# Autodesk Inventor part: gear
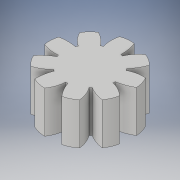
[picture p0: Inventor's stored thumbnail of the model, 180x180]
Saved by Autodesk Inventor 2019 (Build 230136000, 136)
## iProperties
Created: 2019-11
Part Number: gear
Material: Generic
Document SubType Name: Sheet Metal
Designer: PRADYUMNA
Density: 1 g/cm^3
Sheet Metal Rule: Default_mm
Appearance: Default
Author: PRADYUMNA
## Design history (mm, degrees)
sketch "Sketch1"
  geometry: C1 r 10 at (0, 0); 1 further point
  constraints: 1 centre point, 1 coincident
  dimensions: "d0" = 20 diameter of C1
extrude "Extrusion1" new body sketch "Sketch1" distance "d1" = 16; taper "d2" = 0 deg
sketch "Sketch2"
  geometry: A1 r 10 centre (0, 0) between (-9.723, -2.339) and (-9.292, 3.695) reference; A2 r 11.616 centre (-11.172, 9.187) between (-15.973, -1.391) and (-9.723, -2.339); A3 r 10.505 centre (-5.648, 0.543) between (-15.669, 3.695) and (-15.973, -1.391); A4 r 16.108 centre (-12.481, -12.095) between (-9.292, 3.695) and (-15.669, 3.695); 1 further point
  constraints: 8 point on circle, 3 centre point
extrude "Extrusion2" join sketch "Sketch2" distance "d3" = 16; taper "d4" = 0 deg
pattern_circular "Circular Pattern1" dims angle "d6" = 360 deg
body "Solid1"
other parameters: "Thickness" = 0.5, "BendRadius" = 0.5 (= Thickness), "BendReliefWidth" = 0.5 (= Thickness), "BendReliefDepth" = 0.25 (= 0.5 x Thickness), "CornerReliefSize" = 2 (= 4 x Thickness), "SeamGap" = 0.01, "MinimumRemnant" = 1 (= 2 x Thickness), "TransitionRadius" = 0.5 (= BendRadius), "JacobiRadiusSize" = 0.5 (= BendRadius), "GapSize" = 0.5 (= Thickness)
